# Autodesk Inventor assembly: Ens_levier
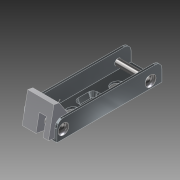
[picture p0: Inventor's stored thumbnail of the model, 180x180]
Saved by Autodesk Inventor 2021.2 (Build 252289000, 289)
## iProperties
Created: 2018-06
Part Number: Ens_levier
Material: Générique
Document SubType Name: Assembly
Designer: Fabian Perrée
Mass: 50.9555 g
Surface Area: 115.259 cm^2
Volume: 10.5334 cm^3
Density: 4.83749 g/cm^3
Author: Fabian Perrée
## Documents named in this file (6)
- C:\Users\Fabian\Google Drive\04_CAO-DAO\01_Exercices\01_Inventor\01_Fichiers_exercice_Inventor\01_Definitif\Capteur\Ens_levier\Ens_levier.iam
- C:\Users\Fabian\Google Drive\04_CAO-DAO\01_Exercices\01_Inventor\01_Fichiers_exercice_Inventor\01_Definitif\Capteur\Ens_levier\Composants\Levier.ipt
- C:\Users\Fabian\Google Drive\04_CAO-DAO\01_Exercices\01_Inventor\01_Fichiers_exercice_Inventor\01_Definitif\Capteur\Ens_levier\Composants\Butee.ipt
- C:\Users\Fabian\Google Drive\04_CAO-DAO\01_Exercices\01_Inventor\01_Fichiers_exercice_Inventor\01_Definitif\Capteur\Ens_levier\Composants\Axe_25.ipt
- C:\Users\Fabian\Google Drive\04_CAO-DAO\01_Exercices\01_Inventor\01_Fichiers_exercice_Inventor\01_Definitif\Capteur\Ens_levier\Composants\Axe_28.ipt
- C:\Users\Fabian\Google Drive\04_CAO-DAO\01_Exercices\01_Inventor\01_Fichiers_exercice_Inventor\01_Definitif\Capteur\Ens_levier\Design Accelerator\Ressort de torsion1.iam
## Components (5 placed, 5 different names)
1. Levier:1 — Placage:4, Logement:2
2. Butee:1 — Tangente:1, Tangente:2
3. Axe_25:1 — Placage:3
4. Axe_28:1 — Logement:2
5. Ressort de torsion:1 [sub-assembly] — Placage:3, Tangente:1, Tangente:2, Placage:4
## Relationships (5: Mate 2, Tangent 2, Insert 1)
- Placage:3 [Mate]: Axe_25:1 ↔ Ressort de torsion:1
- Tangente:1: Butee:1 ↔ Ressort de torsion:1
- Tangente:2: Butee:1 ↔ Ressort de torsion:1
- Placage:4 [Mate]: Levier:1 ↔ Ressort de torsion:1
- Logement:2 [Insert]: Levier:1 ↔ Axe_28:1
